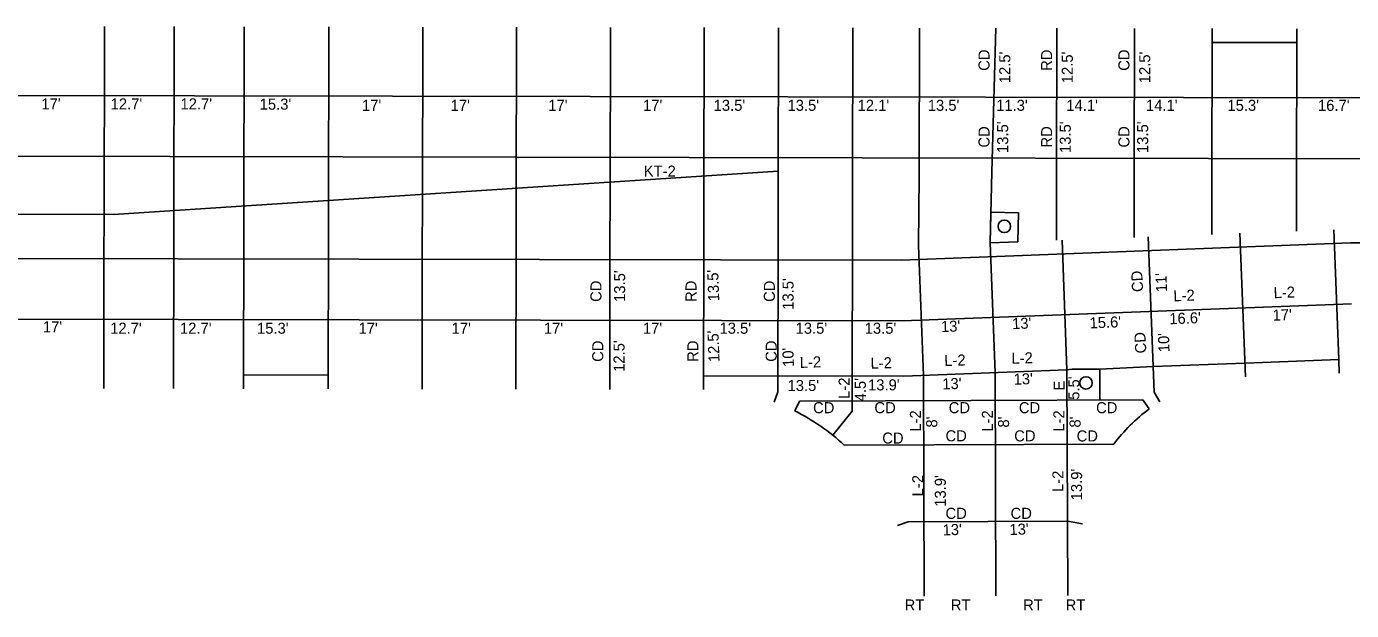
# Model space of a CAD drawing. Extents: x 4995357 to 4999033, y 3881202 to 3881750.
# Drawn here: x 4995852.2 to 4996092.1, y 3881601.3 to 3881707 of the extents above; entities that cross this region are included whole.
import ezdxf

# ---------------------------------------------------------------- set-up
doc = ezdxf.new("R2010")
doc.units = 0
for name, color, linetype in [('dsn3DCenterLine', 7, 'Continuous'), ('dsn3DCurbFormgrade', 7, 'Continuous'), ('dsn3DCurbTop', 7, 'Continuous'), ('dsn3DDitchFront', 7, 'Continuous'), ('dsn3DDNC', 7, 'Continuous'), ('dsn3DExistingPvmtBtm', 7, 'Continuous'), ('dsn3DIntakeWell', 7, 'Continuous')]:
    doc.layers.add(name, color=color, linetype=linetype)

msp = doc.modelspace()

# ---------------------------------------------------------------- linework, layer by layer
at = {"layer": 'dsn3DCurbFormgrade'}
for p, q in [((4995866.26, 3881707.01), (4995866.2, 3881670.51)), ((4995878.92, 3881706.99), (4995878.85, 3881671.21)), ((4995891.57, 3881706.97), (4995891.5, 3881672.03)), ((4995906.9, 3881706.94), (4995906.84, 3881673.03)), ((4995923.89, 3881706.91), (4995923.83, 3881674.13)), ((4995940.88, 3881706.87), (4995940.82, 3881675.23)), ((4995957.87, 3881706.84), (4995957.81, 3881676.33)), ((4995974.81, 3881677.43), (4995974.86, 3881706.81)), ((4995988.26, 3881678.3), (4995988.32, 3881706.79)), ((4996001.72, 3881679.18), (4996001.77, 3881706.76)), ((4996013.85, 3881706.74), (4996013.8, 3881679.96)), ((4996027.67, 3881706.72), (4996026.96, 3881680.72)), ((4996038.69, 3881706.7), (4996038.64, 3881680.7)), ((4996052.75, 3881706.67), (4996052.71, 3881680.67)), ((4996066.77, 3881680.64), (4996066.82, 3881704.14)), ((4996082.11, 3881680.62), (4996082.15, 3881704.12)), ((4996071.86, 3881669.59), (4996072.86, 3881643.61)), ((4996088.85, 3881670.24), (4996089.75, 3881646.75)), ((4995866.19, 3881667.51), (4995866.14, 3881641.51)), ((4995878.84, 3881667.49), (4995878.8, 3881641.49)), ((4995891.5, 3881667.47), (4995891.45, 3881643.97)), ((4995906.83, 3881667.44), (4995906.79, 3881643.94)), ((4995923.82, 3881667.41), (4995923.77, 3881641.41)), ((4995940.81, 3881667.37), (4995940.76, 3881641.38)), ((4995957.8, 3881667.34), (4995957.75, 3881641.34)), ((4995974.74, 3881641.31), (4995974.79, 3881667.31)), ((4995988.2, 3881640.92), (4995988.24, 3881667.29)), ((4996001.66, 3881643.76), (4996001.7, 3881667.26)), ((4996013.65, 3881667.37), (4996014.55, 3881643.88)), ((4996026.65, 3881667.86), (4996027.54, 3881644.38)), ((4996039.65, 3881668.36), (4996040.54, 3881644.87)), ((4996055.24, 3881668.95), (4996056.31, 3881640.81)), ((4996057.37, 3881639.11), (4996056.31, 3881640.81)), ((4995992.14, 3881639.24), (4996054.27, 3881639.44)), ((4995998.15, 3881633.05), (4996001.65, 3881637.4)), ((4996000.22, 3881631.27), (4996049.01, 3881631.42)), ((4996040.63, 3881617.49), (4996011.76, 3881617.4)), ((4996043.34, 3881617.04), (4996040.63, 3881617.49))]:
    msp.add_line(p, q, dxfattribs=at)
at = {"layer": 'dsn3DCurbTop'}
for p, q in [((4996001.7, 3881667.26), (4996001.72, 3881679.18)), ((4996013.8, 3881679.96), (4996013.65, 3881667.37)), ((4996026.96, 3881680.72), (4996026.65, 3881667.86)), ((4996038.64, 3881680.7), (4996038.62, 3881668.36)), ((4996052.71, 3881680.67), (4996052.68, 3881668.85)), ((4996066.77, 3881680.64), (4996066.75, 3881669.39)), ((4996082.11, 3881680.62), (4996082.09, 3881669.98)), ((4995974.79, 3881667.31), (4995974.81, 3881677.43)), ((4995988.26, 3881678.3), (4995988.24, 3881667.29)), ((4995940.81, 3881667.37), (4995940.82, 3881675.23)), ((4995957.81, 3881676.33), (4995957.8, 3881667.34)), ((4995891.5, 3881667.47), (4995891.5, 3881672.03)), ((4995906.84, 3881673.03), (4995906.83, 3881667.44)), ((4995923.82, 3881667.41), (4995923.83, 3881674.13)), ((4995866.2, 3881670.51), (4995866.19, 3881667.51)), ((4995878.85, 3881671.21), (4995878.84, 3881667.49)), ((4995987.51, 3881639.05), (4995988.2, 3881640.92)), ((4995991.25, 3881637.45), (4995992.14, 3881639.24)), ((4996055.45, 3881637.82), (4996054.27, 3881639.44)), ((4996009.88, 3881616.71), (4996011.76, 3881617.4))]:
    msp.add_line(p, q, dxfattribs=at)
at = {"layer": 'dsn3DDitchFront'}
msp.add_lwpolyline([(4995988.27, 3881680.81), (4995867.93, 3881673.01), (4995746.05, 3881673.23)], dxfattribs=at)
at = {"layer": 'dsn3DDNC'}
for p, q in [((4995693.02, 3881694.83), (4996408.86, 3881693.52)), ((4995693.07, 3881683.83), (4996408.76, 3881682.52)), ((4996010.6, 3881664.75), (4996091.85, 3881667.85)), ((4996091.85, 3881667.85), (4996346.03, 3881667.38)), ((4995693.14, 3881665.33), (4996010.6, 3881664.75)), ((4996010.8, 3881653.75), (4996092.05, 3881656.85)), ((4995693.19, 3881654.33), (4996010.8, 3881653.75)), ((4996046.48, 3881645), (4996056.14, 3881645.47)), ((4996056.14, 3881645.47), (4996072.76, 3881646.1)), ((4995974.74, 3881643.81), (4996010.98, 3881643.75)), ((4996001.65, 3881637.4), (4996001.66, 3881643.76)), ((4996010.98, 3881643.75), (4996040.54, 3881644.87)), ((4996014.67, 3881603.94), (4996014.55, 3881643.88)), ((4996027.67, 3881603.98), (4996027.54, 3881644.38)), ((4996040.54, 3881644.87), (4996041.48, 3881645.01)), ((4996040.67, 3881604.02), (4996040.54, 3881644.87))]:
    msp.add_line(p, q, dxfattribs=at)
at = {"layer": 'dsn3DExistingPvmtBtm'}
for points in [[(4996066.82, 3881706.64), (4996066.82, 3881704.14), (4996082.15, 3881704.12), (4996082.15, 3881706.62)], [(4996072.76, 3881646.1), (4996074.43, 3881646.17), (4996089.75, 3881646.75), (4996089.84, 3881644.25)], [(4995891.45, 3881641.47), (4995891.45, 3881643.97), (4995906.79, 3881643.94), (4995906.78, 3881641.44)], [(4996041.48, 3881645.01), (4996046.48, 3881645), (4996046.47, 3881639.41)]]:
    msp.add_lwpolyline(points, dxfattribs=at)
msp.add_lwpolyline([(4996031.77, 3881673.28), (4996031.62, 3881668.05), (4996026.65, 3881667.86), (4996026.77, 3881673.42)], close=True, dxfattribs=at)
for centre in [(4996029.2, 3881670.85), (4996043.98, 3881642.51)]:
    msp.add_circle(centre, 1.12, dxfattribs=at)
at = {"layer": 'dsn3DIntakeWell'}
for p, q in [((4995991.25, 3881637.45), (4995992.14, 3881639.24)), ((4995992.14, 3881639.24), (4996054.27, 3881639.44)), ((4996054.27, 3881639.44), (4996055.45, 3881637.82)), ((4996049.01, 3881631.42), (4996000.22, 3881631.27))]:
    msp.add_line(p, q, dxfattribs=at)
for centre, radius, start, end in [((4995974.67, 3881603.81), 37.5, 47.0615, 63.7548), ((4996073.14, 3881613.59), 30, 126.1464, 143.5494)]:
    msp.add_arc(centre, radius, start, end, dxfattribs=at)

# ---------------------------------------------------------------- texts
at = {"layer": 'dsn3DCenterLine'}
for s, rotation, p in [('CD', 89.9239, (4996026.52, 3881698.99)), ("12.5'", 90, (4996030.28, 3881696.75)), ('RD', 89.9239, (4996037.84, 3881698.99)), ("12.5'", 90, (4996041.6, 3881696.75)), ('CD', 89.9239, (4996051.85, 3881698.99)), ("12.5'", 90, (4996055.61, 3881696.75)), ('CD', 89.9239, (4996026.52, 3881685.1)), ("13.5'", 90, (4996029.9, 3881684.12)), ('RD', 89.9239, (4996037.84, 3881685.1)), ("13.5'", 90, (4996041.23, 3881684.12)), ('CD', 89.9239, (4996051.85, 3881685.1)), ("13.5'", 90, (4996055.24, 3881684.12)), ("13.5'", 90, (4995960.55, 3881657.17)), ("13.5'", 92.1668, (4995977.6, 3881657.32)), ('CD', 93.2116, (4996054.35, 3881659.02)), ("11'", 92.1668, (4996058.67, 3881658.98)), ('CD', 90, (4995956.26, 3881657.17)), ('RD', 90, (4995973.47, 3881657.17)), ('CD', 90, (4995987.66, 3881657.17)), ("13.5'", 90, (4995991.04, 3881655.75)), ('L-2', 2.1855, (4996077.99, 3881657.83)), ('L-2', 2.1855, (4996059.84, 3881657.27)), ("16.6'", 2.1855, (4996059.1, 3881653.12)), ("17'", 2.1855, (4996077.81, 3881653.76)), ("13'", 2.1855, (4996017.77, 3881651.7)), ("13'", 2.1855, (4996030.64, 3881652.23)), ("15.6'", 2.1855, (4996044.66, 3881652.37)), ("12.5'", 92.1668, (4995977.65, 3881646.32)), ('CD', 93.2116, (4996054.92, 3881647.91)), ("10'", 92.1668, (4996059.12, 3881648.11)), ('CD', 90, (4995956.59, 3881646.33)), ("12.5'", 90, (4995960.44, 3881644.51)), ('RD', 90, (4995973.8, 3881646.33)), ('CD', 90, (4995987.99, 3881646.33)), ("10'", 92.1668, (4995991.12, 3881645.45)), ('L-2', 1.7555, (4996030.52, 3881645.96)), ('L-2', 1.7555, (4995992.19, 3881645.22)), ('L-2', 1.7555, (4996005, 3881645.07)), ('L-2', 1.7555, (4996018.35, 3881645.56)), ("13.5'", 0.2007, (4995989.95, 3881641.04)), ('L-2', 90, (4996001.19, 3881639.62)), ("4.5'", 90, (4996004.13, 3881639.17)), ("13.9'", 0.2007, (4996004.53, 3881641.15)), ("13'", 2.1855, (4996018, 3881641.31)), ("13'", 2.1855, (4996030.92, 3881642.17)), ("5.5'", 90, (4996042.78, 3881639.46)), ('E', 90, (4996040.13, 3881641.15)), ('L-2', 90, (4996014.11, 3881633.69)), ("8'", 90, (4996017.05, 3881634.43)), ('L-2', 90, (4996027.13, 3881633.69)), ("8'", 90, (4996030.06, 3881634.43)), ('L-2', 90, (4996040.07, 3881633.69)), ("8'", 90, (4996043, 3881634.43)), ('L-2', 90, (4996039.89, 3881622.77)), ("13.9'", 90, (4996043.28, 3881621.27)), ('L-2', 90, (4996014.53, 3881621.98)), ("13.9'", 90, (4996018.61, 3881620.1)), ("13'", 2.1855, (4996018.06, 3881614.89)), ("13'", 2.1855, (4996030.16, 3881614.97))]:
    msp.add_text(s, height=2, rotation=rotation, dxfattribs=at).set_placement(p)
for s, p in [("17'", (4995854.86, 3881692.01)), ("12.7'", (4995867.4, 3881692.01)), ("12.7'", (4995880.04, 3881692.01)), ("15.3'", (4995894.38, 3881691.96)), ("17'", (4995912.9, 3881691.75)), ("17'", (4995928.95, 3881691.75)), ("17'", (4995946.63, 3881691.75)), ("17'", (4995963.79, 3881691.75)), ("13.5'", (4995976.57, 3881691.75)), ("13.5'", (4995989.94, 3881691.75)), ("12.1'", (4996002.64, 3881691.75)), ("13.5'", (4996015.34, 3881691.75)), ("11.3'", (4996027.72, 3881691.75)), ("14.1'", (4996040.42, 3881691.75)), ("14.1'", (4996054.84, 3881691.75)), ("15.3'", (4996069.59, 3881691.75)), ("16.7'", (4996085.99, 3881691.75)), ('KT-2', (4995963.92, 3881679.85)), ("17'", (4995855.13, 3881651.66)), ("12.7'", (4995867.31, 3881651.41)), ("12.7'", (4995879.95, 3881651.41)), ("15.3'", (4995893.9, 3881651.41)), ("17'", (4995912.27, 3881651.41)), ("17'", (4995929.13, 3881651.41)), ("17'", (4995945.83, 3881651.41)), ("17'", (4995963.76, 3881651.41)), ("13.5'", (4995977.63, 3881651.41)), ("13.5'", (4995991.41, 3881651.41)), ("13.5'", (4996003.92, 3881651.41)), ('CD', (4995994.57, 3881637.03)), ('CD', (4996005.67, 3881637.03)), ('CD', (4996019.13, 3881637.03)), ('CD', (4996031.83, 3881637.03)), ('CD', (4996045.81, 3881637.03)), ('CD', (4996007.1, 3881631.53)), ('CD', (4996018.55, 3881631.94)), ('CD', (4996030.99, 3881631.93)), ('CD', (4996042.29, 3881631.92)), ('CD', (4996018.55, 3881617.91)), ('CD', (4996030.33, 3881617.91)), ('RT', (4996011.15, 3881601.33)), ('RT', (4996019.51, 3881601.33)), ('RT', (4996032.6, 3881601.33)), ('RT', (4996040.3, 3881601.33))]:
    msp.add_text(s, height=2, dxfattribs=at).set_placement(p)

doc.saveas('drawing.dxf')
